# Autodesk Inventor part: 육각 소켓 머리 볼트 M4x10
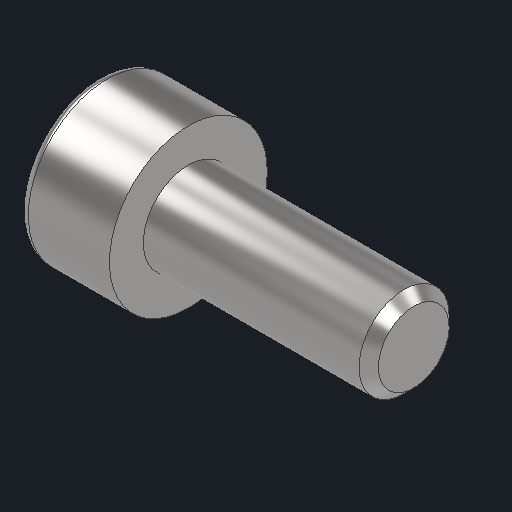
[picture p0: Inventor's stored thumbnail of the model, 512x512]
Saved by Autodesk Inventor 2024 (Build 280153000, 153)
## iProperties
Created: 2024-05
Part Number: 육각 소켓 머리 볼트 M4x10
Material: 강철, 연강
Description: 6각머리 태핑 나사
Document SubType Name: Modeling
Designer: kh_501
Density: 7.85 g/cm^3
Appearance: 기본값
Author: jhkim
Sending System: Autodesk Inventor 2025
Preprocessor: ST-DEVELOPER v20
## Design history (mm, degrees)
feature "Solid1"
node "솔리드1"
